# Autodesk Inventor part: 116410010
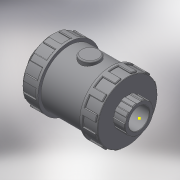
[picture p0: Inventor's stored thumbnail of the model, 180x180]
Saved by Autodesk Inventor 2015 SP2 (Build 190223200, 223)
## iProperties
Created: 2017-11
Part Number: 116410010
Material: Generic
Description: PLASSON FOOT VALVE THR PVC 1"
Document SubType Name: Modeling
Designer: KIM
Density: 1 g/cm^3
Appearance: Default
Author: KIM
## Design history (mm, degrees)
derived "116410 - 116010.ipt"
feature "Solid1::116410 - 116010.ipt"
tag "TaggingFeature1"
body "Solid1"
other parameters: "d0" = 102, "d1" = 30.291, "d2" = 66, "d3" = 19, "d4" = 24.2328, "d5" = 13.3, "d7" = 42.4074, "d8" = 59.4, "d13" = 0.90873, "d23" = 19, "d24" = 63.36, "d25" = 0.60582, "d26" = 0.90873, "d27" = 9.9, "d28" = 4.95, "d29" = 14.25, "d30" = 0, "d35" = 0.90873, "d39" = 33, "d45" = 360 deg, "d47" = 0.60582, "d50" = 33, "d51" = 19.8, "d53" = 0, "d54" = 1.32, "d55" = 6.0582, "d56" = 3.0291, "d58" = 0, "d59" = 0.90873, "d61" = 360 deg, "G_" = 30.291, "l_" = 19, "H_" = 102, "K_" = 66
